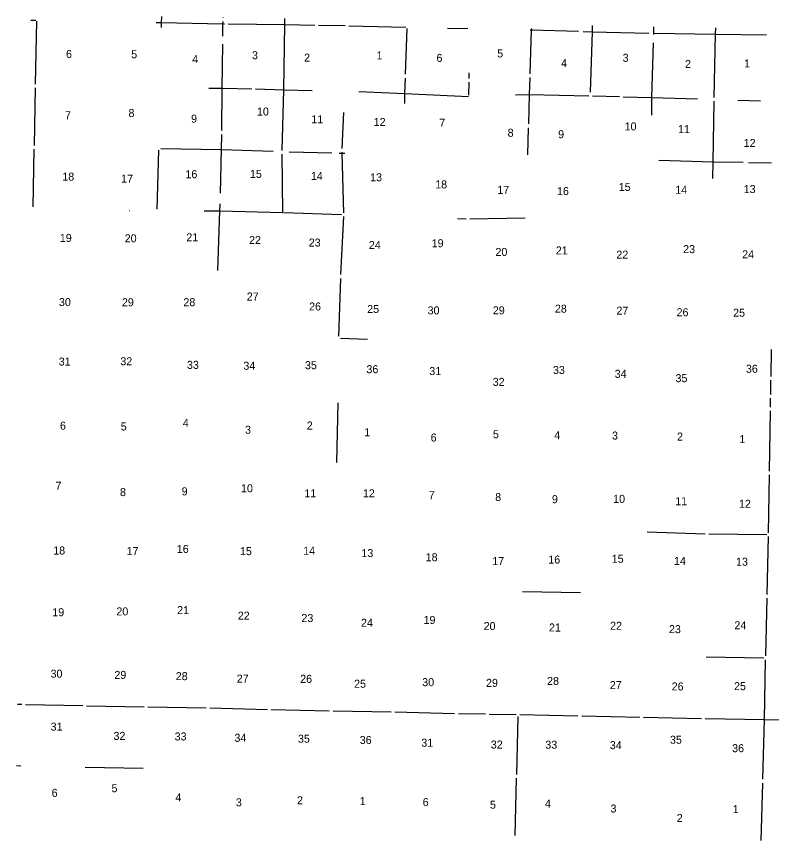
# Model space of a CAD drawing. Extents: x -2933025 to 31692252, y -2344676 to 23854604.
# Drawn here: x -2931501 to -2866805, y -2284720 to -2214069 of the extents above; entities that cross this region are included whole.
import ezdxf

# ---------------------------------------------------------------- set-up
doc = ezdxf.new("R2010")
doc.units = 0
doc.layers.add('tdCoSectLinePart', color=7, linetype='Continuous')
doc.layers.add('tdCoSectNmbr', color=7, linetype='Continuous')

msp = doc.modelspace()

# ---------------------------------------------------------------- linework, layer by layer
at = {"layer": 'tdCoSectLinePart'}
for points in [[(-2919065, -2214597), (-2919061, -2214069)], [(-2913798, -2214173), (-2913798, -2214156)], [(-2930281, -2214372), (-2929856, -2214383)], [(-2929880, -2219867), (-2929756, -2214480)], [(-2919527, -2214589), (-2919065, -2214597)], [(-2919070, -2215008), (-2919065, -2214597)], [(-2919065, -2214597), (-2913808, -2214690)], [(-2913823, -2215769), (-2913808, -2214690)], [(-2913808, -2214690), (-2913804, -2214494)], [(-2913808, -2214690), (-2913689, -2214692)], [(-2913354, -2214696), (-2908514, -2214757)], [(-2908593, -2220348), (-2908514, -2214757)], [(-2908514, -2214757), (-2908514, -2214243)], [(-2908514, -2214757), (-2905946, -2214806)], [(-2905628, -2214812), (-2903345, -2214855)], [(-2903028, -2214862), (-2898131, -2214989)], [(-2882142, -2215376), (-2882138, -2214848)], [(-2898158, -2219006), (-2898026, -2215098)], [(-2894562, -2215071), (-2892816, -2215110)], [(-2887483, -2218981), (-2887379, -2215211)], [(-2887471, -2215210), (-2887379, -2215211)], [(-2887378, -2215096), (-2887379, -2215211)], [(-2887379, -2215211), (-2883356, -2215338)], [(-2882955, -2215350), (-2882142, -2215376)], [(-2882304, -2220548), (-2882142, -2215376)], [(-2882142, -2215376), (-2877321, -2215488)], [(-2876955, -2215496), (-2876890, -2215497)], [(-2876894, -2215627), (-2876890, -2215497)], [(-2876890, -2215497), (-2876883, -2214970)], [(-2876890, -2215497), (-2871594, -2215584)], [(-2871718, -2221021), (-2871594, -2215584)], [(-2871594, -2215584), (-2871586, -2215044)], [(-2871594, -2215584), (-2867248, -2215635)], [(-2913885, -2220214), (-2913833, -2216429)], [(-2877059, -2221027), (-2876915, -2216327)], [(-2892715, -2219376), (-2892708, -2218891)], [(-2898214, -2220670), (-2898170, -2219357)], [(-2892734, -2220814), (-2892719, -2219698)], [(-2887531, -2220752), (-2887492, -2219302)], [(-2929970, -2225136), (-2929886, -2220184)], [(-2915027, -2220202), (-2913885, -2220214)], [(-2913911, -2223855), (-2913885, -2220214)], [(-2913885, -2220214), (-2911349, -2220278)], [(-2911033, -2220286), (-2908593, -2220348)], [(-2908748, -2225571), (-2908593, -2220348)], [(-2908593, -2220348), (-2906153, -2220403)], [(-2902162, -2220513), (-2898214, -2220670)], [(-2898224, -2221544), (-2898214, -2220670)], [(-2898214, -2220670), (-2892774, -2220919)], [(-2888742, -2220791), (-2887531, -2220752)], [(-2887610, -2223285), (-2887531, -2220752)], [(-2887531, -2220752), (-2882466, -2220865)], [(-2882151, -2220873), (-2879822, -2220944)], [(-2879506, -2220953), (-2877059, -2221027)], [(-2877071, -2222533), (-2877059, -2221027)], [(-2877059, -2221027), (-2873148, -2221139)], [(-2869704, -2221245), (-2867737, -2221308)], [(-2871808, -2226519), (-2871724, -2221338)], [(-2903583, -2225387), (-2903440, -2222305)], [(-2887692, -2225931), (-2887620, -2223603)], [(-2913923, -2225488), (-2913914, -2224192)], [(-2930078, -2230404), (-2929976, -2225453)], [(-2919147, -2225397), (-2913923, -2225488)], [(-2914024, -2229214), (-2913923, -2225488)], [(-2913923, -2225488), (-2909499, -2225620)], [(-2919454, -2230589), (-2919295, -2225532)], [(-2908682, -2230882), (-2908747, -2225888)], [(-2908140, -2225660), (-2904471, -2225763)], [(-2903851, -2225781), (-2903602, -2225788)], [(-2903602, -2225788), (-2903598, -2225704)], [(-2903602, -2225788), (-2903357, -2225796)], [(-2903451, -2230911), (-2903602, -2225788)], [(-2876465, -2226378), (-2871808, -2226519)], [(-2871831, -2227962), (-2871808, -2226519)], [(-2871808, -2226519), (-2869225, -2226574)], [(-2868768, -2226584), (-2866812, -2226625)], [(-2914066, -2230743), (-2914049, -2230133)], [(-2921858, -2230705), (-2921807, -2230706)], [(-2915430, -2230744), (-2914066, -2230743)], [(-2914253, -2235841), (-2914066, -2230743)], [(-2914066, -2230743), (-2908682, -2230882)], [(-2908683, -2230902), (-2908682, -2230882)], [(-2908682, -2230882), (-2908640, -2230884)], [(-2908600, -2230885), (-2903665, -2231060)], [(-2903700, -2236204), (-2903454, -2231228)], [(-2893705, -2231401), (-2892977, -2231425)], [(-2892657, -2231427), (-2887902, -2231345)], [(-2903887, -2241492), (-2903714, -2236521)], [(-2903734, -2241654), (-2901422, -2241726)], [(-2866847, -2244927), (-2866808, -2242612)], [(-2866874, -2246484), (-2866852, -2245243)], [(-2904045, -2252307), (-2903945, -2247191)], [(-2866892, -2247566), (-2866879, -2246801)], [(-2866979, -2253058), (-2866897, -2247880)], [(-2867057, -2258335), (-2866984, -2253374)], [(-2877468, -2258267), (-2872489, -2258415)], [(-2872172, -2258421), (-2867217, -2258491)], [(-2867165, -2263617), (-2867062, -2258652)], [(-2888138, -2263380), (-2883167, -2263458)], [(-2867303, -2268900), (-2867173, -2263933)], [(-2872401, -2268976), (-2867465, -2269057)], [(-2867418, -2274344), (-2867310, -2269216)], [(-2931402, -2273031), (-2931033, -2273039)], [(-2930717, -2273046), (-2925811, -2273154)], [(-2925495, -2273160), (-2920551, -2273253)], [(-2920234, -2273258), (-2915262, -2273334)], [(-2914946, -2273341), (-2909992, -2273480)], [(-2909676, -2273488), (-2904697, -2273595)], [(-2904378, -2273601), (-2899399, -2273689)], [(-2899081, -2273696), (-2893956, -2273829)], [(-2893637, -2273836), (-2891310, -2273872)], [(-2890993, -2273877), (-2888674, -2273914)], [(-2888637, -2279067), (-2888517, -2274075)], [(-2888357, -2273920), (-2883388, -2274031)], [(-2883072, -2274038), (-2878089, -2274141)], [(-2877773, -2274147), (-2872815, -2274245)], [(-2872499, -2274251), (-2867418, -2274344)], [(-2867544, -2279472), (-2867418, -2274344)], [(-2867418, -2274344), (-2862357, -2274442)], [(-2931501, -2278299), (-2931132, -2278308)], [(-2925618, -2278425), (-2920650, -2278525)], [(-2888780, -2284276), (-2888646, -2279384)], [(-2867696, -2284720), (-2867553, -2279789)]]:
    msp.add_lwpolyline(points, dxfattribs=at)

# ---------------------------------------------------------------- texts
at = {"layer": 'tdCoSectNmbr'}
for s, height, rotation, p in [('6', 686, 359.92674, (-2927258, -2217627)), ('5', 686, 359.92755, (-2921672, -2217652)), ('5', 686, 359.93108, (-2890309, -2217580)), ('4', 686, 359.92831, (-2916445, -2218059)), ('3', 686, 359.92905, (-2911320, -2217734)), ('2', 686, 359.9297, (-2906857, -2217936)), ('1', 686, 359.93059, (-2900651, -2217756)), ('6', 686, 359.93134, (-2895512, -2217963)), ('4', 686, 359.93187, (-2884835, -2218405)), ('3', 686, 359.93263, (-2879563, -2217954)), ('2', 686, 359.93341, (-2874219, -2218476)), ('1', 686, 359.93413, (-2869154, -2218434)), ('10', 686.4, 359.92911, (-2910895, -2222563)), ('7', 686, 359.9267, (-2927348, -2222882)), ('8', 686, 359.92749, (-2921903, -2222687)), ('9', 686, 359.92827, (-2916542, -2223176)), ('11', 686.4, 359.92978, (-2906238, -2223220)), ('12', 686.4, 359.93055, (-2900896, -2223453)), ('7', 686, 359.93134, (-2895275, -2223524)), ('10', 686.4, 359.93273, (-2879393, -2223839)), ('11', 686.4, 359.93339, (-2874812, -2224064)), ('8', 686, 359.93134, (-2889417, -2224381)), ('9', 686, 359.93189, (-2885088, -2224504)), ('12', 686.4, 359.93409, (-2869192, -2225256)), ('18', 686.4, 359.92661, (-2927574, -2228139)), ('16', 686.4, 359.9282, (-2917025, -2227935)), ('15', 686.4, 359.929, (-2911500, -2227908)), ('14', 686.4, 359.92976, (-2906275, -2228087)), ('13', 686.4, 359.93051, (-2901199, -2228197)), ('17', 686.4, 359.92738, (-2922535, -2228318)), ('18', 686.4, 359.9313, (-2895624, -2228809)), ('17', 686.4, 359.93119, (-2890301, -2229275)), ('16', 686.4, 359.93194, (-2885188, -2229381)), ('15', 686.4, 359.9327, (-2879895, -2229025)), ('14', 686.4, 359.93341, (-2875058, -2229272)), ('13', 686.4, 359.93429, (-2869188, -2229209)), ('19', 686.4, 359.92661, (-2927788, -2233393)), ('20', 686.4, 359.92742, (-2922229, -2233432)), ('21', 686.4, 359.92818, (-2916947, -2233344)), ('22', 686.4, 359.92896, (-2911575, -2233578)), ('23', 686.4, 359.9297, (-2906459, -2233796)), ('19', 686.4, 359.93123, (-2895924, -2233853)), ('24', 686.4, 359.93044, (-2901309, -2234002)), ('20', 686.4, 359.93124, (-2890460, -2234599)), ('21', 686.4, 359.93197, (-2885286, -2234471)), ('23', 686.4, 359.93355, (-2874378, -2234357)), ('22', 686.4, 359.93273, (-2880105, -2234829)), ('24', 686.4, 359.93428, (-2869319, -2234806)), ('30', 686.4, 359.92658, (-2927866, -2238899)), ('29', 686.4, 359.92736, (-2922469, -2238914)), ('28', 686.4, 359.92812, (-2917201, -2238907)), ('27', 686.4, 359.92891, (-2911773, -2238421)), ('26', 686.4, 359.92968, (-2906430, -2239275)), ('25', 686.4, 359.9304, (-2901452, -2239489)), ('30', 686.4, 359.93115, (-2896275, -2239611)), ('29', 686.4, 359.93125, (-2890686, -2239609)), ('28', 686.4, 359.93202, (-2885367, -2239462)), ('27', 686.4, 359.93278, (-2880094, -2239634)), ('26', 686.4, 359.93352, (-2874940, -2239770)), ('25', 686.4, 359.93422, (-2870096, -2239809)), ('31', 686.4, 359.92654, (-2927884, -2243998)), ('32', 686.4, 359.92731, (-2922605, -2243973)), ('33', 686.4, 359.92814, (-2916894, -2244280)), ('34', 686.4, 359.92884, (-2912061, -2244359)), ('35', 686.4, 359.9296, (-2906786, -2244309)), ('36', 686.4, 359.93036, (-2901517, -2244654)), ('31', 686.4, 359.93114, (-2896131, -2244813)), ('33', 686.4, 359.93204, (-2885534, -2244718)), ('34', 686.4, 359.93281, (-2880241, -2245050)), ('36', 686.4, 359.93443, (-2868999, -2244616)), ('32', 686.4, 359.93133, (-2890695, -2245739)), ('35', 686.4, 359.93355, (-2875032, -2245422)), ('6', 686, 359.92652, (-2927779, -2249493)), ('4', 686, 359.92804, (-2917251, -2249254)), ('2', 686, 359.92958, (-2906629, -2249481)), ('5', 686, 359.92727, (-2922570, -2249562)), ('3', 686, 359.92881, (-2911920, -2249843)), ('1', 686, 359.93028, (-2901704, -2250054)), ('6', 686, 359.93111, (-2896013, -2250510)), ('5', 686, 359.93133, (-2890670, -2250229)), ('4', 686, 359.93209, (-2885419, -2250310)), ('3', 686, 359.9328, (-2880472, -2250340)), ('2', 686, 359.93361, (-2874901, -2250428)), ('1', 686, 359.93439, (-2869570, -2250651)), ('7', 686, 359.92644, (-2928159, -2254638)), ('9', 686, 359.928, (-2917347, -2255123)), ('10', 686.4, 359.92876, (-2912263, -2254861)), ('8', 686, 359.92724, (-2922634, -2255190)), ('11', 686.4, 359.92954, (-2906834, -2255297)), ('12', 686.4, 359.93027, (-2901819, -2255295)), ('7', 686, 359.93106, (-2896176, -2255458)), ('8', 686, 359.93141, (-2890483, -2255613)), ('9', 686, 359.93211, (-2885621, -2255798)), ('10', 686.4, 359.93287, (-2880376, -2255768)), ('11', 686.4, 359.93364, (-2875056, -2255973)), ('12', 686.4, 359.93444, (-2869594, -2256188)), ('16', 686.4, 359.92794, (-2917766, -2260064)), ('18', 686.4, 359.92641, (-2928356, -2260198)), ('17', 686.4, 359.92732, (-2922070, -2260251)), ('15', 686.4, 359.92872, (-2912354, -2260253)), ('14', 686.4, 359.92951, (-2906936, -2260220)), ('13', 686.4, 359.93023, (-2901949, -2260417)), ('18', 686.4, 359.93102, (-2896439, -2260774)), ('17', 686.4, 359.93144, (-2890739, -2261110)), ('16', 686.4, 359.93214, (-2885931, -2260972)), ('15', 686.4, 359.9329, (-2880498, -2260904)), ('14', 686.4, 359.93368, (-2875164, -2261094)), ('13', 686.4, 359.93446, (-2869845, -2261158)), ('19', 686.4, 359.92637, (-2928435, -2265487)), ('20', 686.4, 359.92717, (-2922944, -2265419)), ('21', 686.4, 359.92791, (-2917734, -2265305)), ('22', 686.4, 359.92867, (-2912541, -2265784)), ('23', 686.4, 359.92946, (-2907088, -2265988)), ('24', 686.4, 359.93019, (-2901983, -2266394)), ('19', 686.4, 359.93097, (-2896623, -2266154)), ('20', 686.4, 359.93142, (-2891473, -2266677)), ('21', 686.4, 359.93219, (-2885875, -2266799)), ('22', 686.4, 359.93294, (-2880638, -2266650)), ('23', 686.4, 359.93371, (-2875593, -2266940)), ('24', 686.4, 359.93449, (-2869983, -2266608)), ('30', 686.4, 359.92633, (-2928582, -2270757)), ('29', 686.4, 359.92711, (-2923114, -2270863)), ('28', 686.4, 359.92788, (-2917854, -2270971)), ('27', 686.4, 359.92863, (-2912628, -2271183)), ('26', 686.4, 359.92942, (-2907195, -2271202)), ('28', 686.4, 359.93222, (-2886036, -2271383)), ('25', 686.4, 359.93008, (-2902575, -2271621)), ('30', 686.4, 359.93093, (-2896733, -2271486)), ('29', 686.4, 359.93146, (-2891269, -2271546)), ('27', 686.4, 359.933, (-2880658, -2271735)), ('26', 686.4, 359.93376, (-2875359, -2271853)), ('25', 686.4, 359.93452, (-2870016, -2271828)), ('31', 686.4, 359.92632, (-2928577, -2275303)), ('32', 686.4, 359.9271, (-2923191, -2276091)), ('33', 686.4, 359.92786, (-2917952, -2276140)), ('34', 686.4, 359.9286, (-2912825, -2276258)), ('35', 686.4, 359.92938, (-2907386, -2276332)), ('36', 686.4, 359.93015, (-2902092, -2276445)), ('31', 686.4, 359.9309, (-2896814, -2276680)), ('32', 686.4, 359.93158, (-2890862, -2276833)), ('33', 686.4, 359.93225, (-2886189, -2276847)), ('34', 686.4, 359.93304, (-2880662, -2276886)), ('35', 686.4, 359.93378, (-2875505, -2276422)), ('36', 686.4, 359.93455, (-2870179, -2277148)), ('5', 686, 359.92709, (-2923361, -2280578)), ('6', 686, 359.92631, (-2928488, -2280975)), ('4', 686, 359.92784, (-2917885, -2281362)), ('3', 686, 359.92858, (-2912704, -2281788)), ('2', 686, 359.92934, (-2907464, -2281614)), ('1', 686, 359.93011, (-2902093, -2281679)), ('6', 686, 359.9309, (-2896693, -2281770)), ('5', 686, 359.9316, (-2890931, -2281989)), ('4', 686, 359.93227, (-2886217, -2281891)), ('3', 686, 359.93306, (-2880604, -2282320)), ('1', 686, 359.93456, (-2870129, -2282372)), ('2', 686, 359.93383, (-2874927, -2283134))]:
    msp.add_text(s, height=height, rotation=rotation, dxfattribs=at).set_placement(p)

doc.saveas('drawing.dxf')
